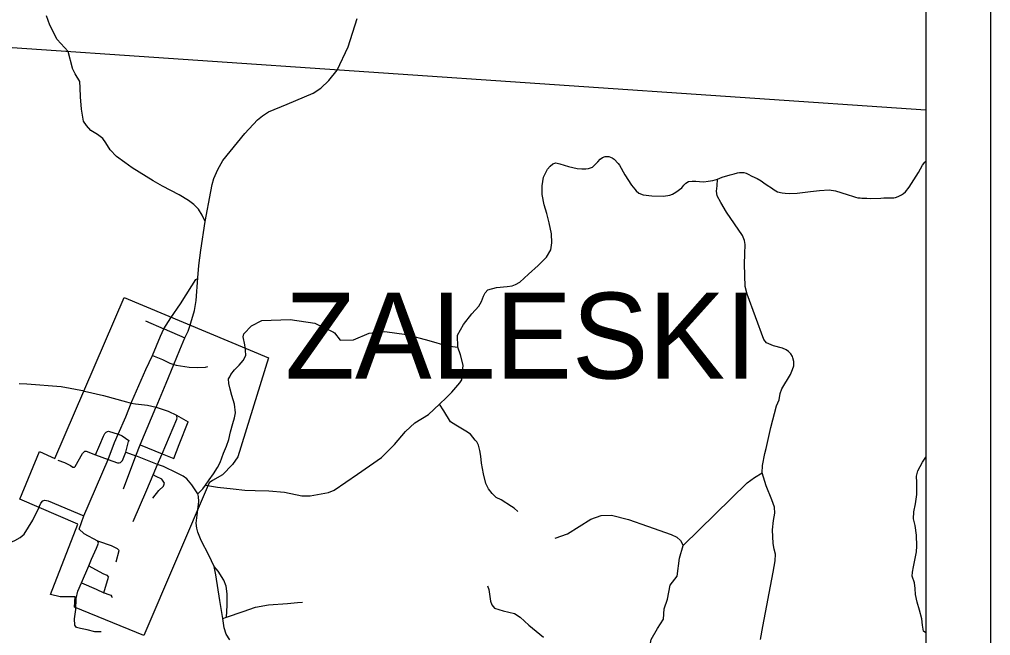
# Model space of a CAD drawing. Extents: x -22 to 431, y -18 to 160.
# Drawn here: x -16.478 to -14.978, y 26.647 to 27.599 of the extents above; entities that cross this region are included whole.
import ezdxf

# ---------------------------------------------------------------- set-up
doc = ezdxf.new("R2010")
doc.units = 0
for name, color, linetype in [('GM_X_Adjacent_County_Text', 7, 'Continuous'), ('GM_X_County_Road', 7, 'Continuous'), ('GM_X_County_ROW', 7, 'Continuous'), ('GM_X_County_Subdivision_Text', 7, 'Continuous'), ('GM_X_Interstate_Location', 7, 'Continuous'), ('GM_X_Major_River_Text', 7, 'Continuous'), ('GM_X_Minor_River_Text', 7, 'Continuous'), ('GM_X_Section', 7, 'Continuous'), ('GM_X_Section_Text', 7, 'Continuous'), ('GM_X_Township_ROW', 7, 'Continuous')]:
    doc.layers.add(name, color=color, linetype=linetype)

msp = doc.modelspace()

# ---------------------------------------------------------------- linework, layer by layer
at = {"layer": 'GM_X_Adjacent_County_Text'}
for points in [[(-16.3966, 27.5233), (-16.4032, 27.549), (-16.4203, 27.5675), (-16.4314, 27.5899), (-16.4368, 27.6045)], [(-16.1912, 27.2868), (-16.196, 27.2963), (-16.2017, 27.3056), (-16.2088, 27.3131), (-16.217, 27.3191), (-16.2316, 27.3279), (-16.2571, 27.3412), (-16.2716, 27.3495), (-16.3041, 27.3695), (-16.3153, 27.3776), (-16.3285, 27.387), (-16.3382, 27.3974), (-16.3449, 27.4079), (-16.3493, 27.4149), (-16.3575, 27.4211), (-16.368, 27.4271), (-16.3745, 27.4347), (-16.3793, 27.4417), (-16.3827, 27.4602), (-16.3841, 27.4793), (-16.3844, 27.493), (-16.3851, 27.5028), (-16.392, 27.5147), (-16.3965, 27.5229), (-16.3966, 27.5233)]]:
    msp.add_lwpolyline(points, dxfattribs=at)
at = {"layer": 'GM_X_County_Road'}
for points in [[(-16.1534, 27.0469), (-16.1517, 27.0502), (-16.1459, 27.0576), (-16.1386, 27.0645), (-16.1324, 27.0717), (-16.1287, 27.0795), (-16.1289, 27.0881), (-16.1303, 27.096), (-16.1325, 27.1085), (-16.1318, 27.1131), (-16.12, 27.1255), (-16.1036, 27.1336), (-16.06, 27.1352), (-16.0221, 27.1294), (-15.9929, 27.1158), (-15.9915, 27.1147), (-15.9826, 27.1032), (-15.9623, 27.1041), (-15.9378, 27.1143), (-15.9138, 27.1168), (-15.88, 27.1119), (-15.8457, 27.1027), (-15.8174, 27.0945), (-15.8009, 27.0927)], [(-15.5078, 26.8161), (-15.471, 26.8032), (-15.4627, 26.7993), (-15.4568, 26.7937), (-15.4526, 26.7863), (-15.3536, 26.8832), (-15.3424, 26.8915), (-15.3306, 26.8986)], [(-15.6505, 26.7975), (-15.6313, 26.8044), (-15.5953, 26.827), (-15.5796, 26.8325), (-15.5633, 26.8332), (-15.5372, 26.8265), (-15.5078, 26.8161)], [(-15.515, 26.5598), (-15.5145, 26.5612), (-15.5123, 26.5673), (-15.5034, 26.5778), (-15.5007, 26.5874), (-15.5053, 26.6078), (-15.5053, 26.623), (-15.502, 26.6409), (-15.4924, 26.6579), (-15.4831, 26.6724), (-15.4818, 26.6882), (-15.4771, 26.7031), (-15.4725, 26.7249), (-15.4621, 26.7389), (-15.4582, 26.7667), (-15.4526, 26.7863)], [(-15.7548, 26.7239), (-15.7528, 26.7185), (-15.7506, 26.7005), (-15.7482, 26.6944), (-15.7444, 26.6892), (-15.7309, 26.6853), (-15.7135, 26.6814), (-15.7046, 26.6758), (-15.691, 26.6634), (-15.6685, 26.6448)]]:
    msp.add_lwpolyline(points, dxfattribs=at)
at = {"layer": 'GM_X_County_ROW'}
for points in [[(-16.2151, 27.1252), (-16.2151, 27.1252), (-16.2079, 27.1494), (-16.2055, 27.1645), (-16.2026, 27.1998), (-16.2012, 27.2188), (-16.1981, 27.2426), (-16.1912, 27.2868), (-16.1827, 27.333), (-16.1807, 27.3438), (-16.178, 27.353), (-16.1718, 27.3669), (-16.1641, 27.3811), (-16.1298, 27.4227), (-16.1105, 27.4435), (-16.1027, 27.4499), (-16.0933, 27.456), (-16.0647, 27.4679), (-16.0246, 27.4847), (-16.0128, 27.4925), (-16, 27.5042), (-15.9876, 27.5206), (-15.9704, 27.5563), (-15.9565, 27.6004)], [(-16.2304, 27.0883), (-16.2228, 27.107), (-16.2175, 27.1172), (-16.2151, 27.1252)], [(-16.2674, 26.9995), (-16.2673, 26.9998), (-16.2514, 27.0367), (-16.2396, 27.0658), (-16.2304, 27.0883)], [(-16.2986, 26.9247), (-16.2916, 26.9415), (-16.2745, 26.9832), (-16.2675, 26.9995), (-16.2674, 26.9995)], [(-16.4481, 26.8452), (-16.4472, 26.8471), (-16.4451, 26.8514), (-16.4421, 26.8553), (-16.4391, 26.8565), (-16.434, 26.8554), (-16.3787, 26.832), (-16.341, 26.9192), (-16.327, 26.9141), (-16.3244, 26.9138), (-16.3221, 26.9146), (-16.3193, 26.9176), (-16.3137, 26.9305), (-16.2986, 26.9247)], [(-16.2537, 26.907), (-16.2537, 26.907), (-16.256, 26.908), (-16.2648, 26.9114), (-16.2986, 26.9247)], [(-16.2026, 26.8659), (-16.2056, 26.8706), (-16.2118, 26.8801), (-16.2196, 26.8893), (-16.2255, 26.8935), (-16.2365, 26.899), (-16.2537, 26.907)], [(-16.1532, 26.6406), (-16.1588, 26.6492), (-16.1619, 26.6589), (-16.1642, 26.6734), (-16.1689, 26.7012), (-16.175, 26.7408), (-16.1772, 26.754), (-16.1858, 26.7711), (-16.1975, 26.7937), (-16.2026, 26.8067), (-16.2043, 26.8131), (-16.2052, 26.8205), (-16.2025, 26.8414), (-16.2013, 26.8543), (-16.2014, 26.8617), (-16.2026, 26.8659)], [(-16.6958, 26.7206), (-16.6958, 26.7206), (-16.6767, 26.7252), (-16.6648, 26.7275), (-16.6534, 26.7331), (-16.6403, 26.742), (-16.6345, 26.7471), (-16.6308, 26.7505), (-16.6251, 26.7541), (-16.6051, 26.7605), (-16.5616, 26.7746), (-16.5542, 26.7758), (-16.5236, 26.7798), (-16.5155, 26.782), (-16.5012, 26.7874), (-16.4855, 26.7942), (-16.4773, 26.7985), (-16.4711, 26.8037), (-16.4575, 26.8254), (-16.4481, 26.8452)]]:
    msp.add_lwpolyline(points, dxfattribs=at)
at = {"layer": 'GM_X_County_Subdivision_Text'}
msp.add_lwpolyline([(-16.2862, 26.6473), (-16.3932, 26.6908), (-16.3924, 26.7069), (-16.4155, 26.7069), (-16.4304, 26.7105), (-16.388, 26.8194), (-16.4778, 26.8579), (-16.4475, 26.9314), (-16.4235, 26.9208), (-16.3164, 27.169), (-16.0936, 27.0762), (-16.1408, 26.9233), (-16.1492, 26.9112), (-16.1644, 26.8952), (-16.1799, 26.8865), (-16.1853, 26.8828)], close=True, dxfattribs=at)
at = {"layer": 'GM_X_Major_River_Text'}
msp.add_line((-15.0776, 27.4585), (-16.6991, 27.5692), dxfattribs=at)
at = {"layer": 'GM_X_Minor_River_Text'}
for points in [[(-15.8291, 27.0045), (-15.8186, 27.0148), (-15.81, 27.0233), (-15.7978, 27.0377), (-15.7949, 27.0419), (-15.7928, 27.065), (-15.7969, 27.0808), (-15.8009, 27.0927), (-15.8014, 27.1113), (-15.7922, 27.1273), (-15.779, 27.1438), (-15.7686, 27.1557), (-15.7641, 27.1633), (-15.761, 27.1713), (-15.7588, 27.1763), (-15.7543, 27.1809), (-15.7411, 27.1847), (-15.7247, 27.1864), (-15.7169, 27.1873), (-15.7118, 27.1892), (-15.7052, 27.1931), (-15.6918, 27.2053), (-15.6768, 27.2189), (-15.6641, 27.2314), (-15.6573, 27.2429), (-15.6555, 27.2536), (-15.6559, 27.2674), (-15.6596, 27.2844), (-15.6636, 27.299), (-15.6675, 27.3122), (-15.6708, 27.3283), (-15.6706, 27.3416), (-15.6684, 27.3549), (-15.6623, 27.3673), (-15.658, 27.3719), (-15.6539, 27.3756), (-15.6492, 27.3772), (-15.6434, 27.3755), (-15.6299, 27.3714), (-15.6166, 27.3683), (-15.609, 27.3678), (-15.603, 27.3681), (-15.5988, 27.3687), (-15.5928, 27.3705), (-15.589, 27.374), (-15.5845, 27.3788), (-15.5808, 27.3828), (-15.5771, 27.3855), (-15.5733, 27.3869), (-15.5676, 27.3872), (-15.5623, 27.3851), (-15.5592, 27.3829), (-15.5532, 27.3763), (-15.5513, 27.3737), (-15.5429, 27.3588), (-15.5325, 27.343), (-15.5276, 27.3365), (-15.5253, 27.334), (-15.5211, 27.3303), (-15.5144, 27.3279), (-15.5011, 27.3262), (-15.4831, 27.3258), (-15.4733, 27.3275), (-15.4692, 27.3291), (-15.4641, 27.3318), (-15.4549, 27.3384), (-15.4514, 27.343), (-15.4485, 27.3456), (-15.4446, 27.3482), (-15.4387, 27.349), (-15.4332, 27.3491), (-15.4272, 27.3484), (-15.4209, 27.3481), (-15.4139, 27.3488), (-15.4069, 27.3502), (-15.3995, 27.352), (-15.3922, 27.3549), (-15.3801, 27.3589), (-15.3739, 27.3603), (-15.3686, 27.3617), (-15.3656, 27.3621), (-15.3618, 27.3623), (-15.3589, 27.3622), (-15.3553, 27.3613), (-15.3523, 27.3598), (-15.3467, 27.3569), (-15.3383, 27.3528), (-15.3322, 27.3493), (-15.328, 27.3465), (-15.3227, 27.3429), (-15.3163, 27.3385), (-15.3119, 27.3353), (-15.3094, 27.3338), (-15.307, 27.3325), (-15.2995, 27.3307), (-15.2952, 27.3302), (-15.2891, 27.3299), (-15.2764, 27.3303), (-15.256, 27.3328), (-15.2422, 27.3347), (-15.227, 27.3353), (-15.217, 27.3339), (-15.1994, 27.3284), (-15.1893, 27.325), (-15.1861, 27.324), (-15.1829, 27.3233), (-15.1793, 27.323), (-15.1766, 27.3228), (-15.1732, 27.3227), (-15.169, 27.3227), (-15.1635, 27.3224), (-15.147, 27.3228), (-15.1425, 27.3231), (-15.1378, 27.3234), (-15.127, 27.3233), (-15.1243, 27.3237), (-15.1204, 27.3253), (-15.1151, 27.3278), (-15.1119, 27.33), (-15.1091, 27.3323), (-15.1033, 27.3396), (-15.0892, 27.3625), (-15.0828, 27.3738), (-15.0794, 27.3782), (-15.0776, 27.38)], [(-15.3245, 26.9362), (-15.3174, 26.9684), (-15.3086, 27.0019), (-15.3042, 27.0113), (-15.303, 27.021), (-15.3003, 27.028), (-15.2869, 27.0502), (-15.2835, 27.058), (-15.2818, 27.0637), (-15.2817, 27.0702), (-15.2832, 27.0761), (-15.2839, 27.0781), (-15.2863, 27.0823), (-15.2899, 27.086), (-15.2934, 27.0883), (-15.2991, 27.091), (-15.3128, 27.0948), (-15.324, 27.0991), (-15.3281, 27.1045), (-15.3538, 27.1746), (-15.3566, 27.1863), (-15.3577, 27.2208), (-15.3575, 27.2368), (-15.3568, 27.251), (-15.358, 27.2573), (-15.3611, 27.265), (-15.3857, 27.3011), (-15.3945, 27.3162), (-15.3999, 27.3264), (-15.401, 27.3336), (-15.4002, 27.3419), (-15.3995, 27.352)], [(-16.2442, 27.1378), (-16.2297, 27.1596), (-16.2119, 27.1874), (-16.2056, 27.1969), (-16.2027, 27.1987)], [(-16.1909, 26.8794), (-16.1851, 26.8878), (-16.1786, 26.8969), (-16.1724, 26.9065), (-16.1681, 26.9143), (-16.1631, 26.9287), (-16.1585, 26.9397), (-16.155, 26.95), (-16.1521, 26.962), (-16.1488, 26.9745), (-16.146, 26.9836), (-16.1447, 26.991), (-16.1462, 27.0043), (-16.1501, 27.0177), (-16.1526, 27.0276), (-16.155, 27.0365), (-16.1552, 27.0435), (-16.1534, 27.0468), (-16.1534, 27.0469)], [(-16.378, 27.0248), (-16.4138, 27.0313), (-16.4672, 27.0352), (-16.479, 27.0361)], [(-16.2026, 26.8659), (-16.1952, 26.8735), (-16.1909, 26.8794), (-16.1721, 26.8761), (-16.1483, 26.8735), (-16.1303, 26.8717), (-16.1142, 26.8711), (-16.0932, 26.8705), (-16.0687, 26.8687), (-16.0422, 26.8627), (-16.0289, 26.8628), (-16.0008, 26.8679), (-15.9919, 26.8716), (-15.956, 26.8965), (-15.9189, 26.9224), (-15.8988, 26.942), (-15.8818, 26.9625), (-15.8675, 26.9755), (-15.8464, 26.9887), (-15.8291, 27.0045)], [(-15.7081, 26.8388), (-15.714, 26.8438), (-15.7178, 26.8464), (-15.7337, 26.8568), (-15.7414, 26.8605), (-15.7477, 26.8667), (-15.7537, 26.8735), (-15.7578, 26.8821), (-15.7612, 26.8967), (-15.7641, 26.9134), (-15.7652, 26.9242), (-15.7671, 26.9331), (-15.7691, 26.9414), (-15.7716, 26.9461), (-15.774, 26.9487), (-15.7811, 26.9581), (-15.7883, 26.9627), (-15.8041, 26.9723), (-15.812, 26.9773), (-15.8226, 26.9943), (-15.8291, 27.0045)], [(-15.3333, 26.6412), (-15.3293, 26.6613), (-15.3134, 26.7453), (-15.3103, 26.7626), (-15.3102, 26.7726), (-15.3122, 26.7806), (-15.3137, 26.7891), (-15.3144, 26.8103), (-15.3131, 26.825), (-15.3111, 26.836), (-15.3116, 26.8455), (-15.3154, 26.8568), (-15.3243, 26.8783), (-15.3286, 26.8918), (-15.3306, 26.8986), (-15.3302, 26.91), (-15.3262, 26.9285), (-15.3245, 26.9362)], [(-15.0776, 26.6511), (-15.081, 26.654), (-15.0827, 26.6631), (-15.0836, 26.6729), (-15.0874, 26.6865), (-15.091, 26.6986), (-15.0934, 26.7104), (-15.0941, 26.7197), (-15.095, 26.7288), (-15.0988, 26.7388), (-15.0981, 26.7452), (-15.0967, 26.7532), (-15.0923, 26.7762), (-15.0917, 26.7854), (-15.0919, 26.8024), (-15.0942, 26.817), (-15.0965, 26.8276), (-15.096, 26.8383), (-15.0938, 26.8506), (-15.0917, 26.8651), (-15.0914, 26.8738), (-15.0916, 26.8837), (-15.0921, 26.8932), (-15.0901, 26.9015), (-15.0826, 26.9149), (-15.0776, 26.9226)], [(-16.3521, 26.6529), (-16.3621, 26.6527), (-16.3739, 26.6562), (-16.3839, 26.6582), (-16.39, 26.6597), (-16.3927, 26.6631), (-16.3933, 26.6729), (-16.3914, 26.6875)], [(-16.1642, 26.6734), (-16.1582, 26.6757), (-16.1328, 26.6842), (-16.1137, 26.6911), (-16.0934, 26.6947), (-16.0641, 26.6969), (-16.0488, 26.6982), (-16.0407, 26.6986)]]:
    msp.add_lwpolyline(points, dxfattribs=at)
at = {"layer": 'GM_X_Section'}
for p, q in [((-14.9776, 29.1642), (-14.9776, 22.1642)), ((-15.0776, 29.0642), (-15.0776, 22.2642)), ((-15.0776, 29.0642), (-15.0776, 22.2642))]:
    msp.add_line(p, q, dxfattribs=at)
at = {"layer": 'GM_X_Section_Text'}
for points in [[(-16.3046, 27.0088), (-16.283, 27.0582), (-16.273, 27.0799), (-16.2604, 27.1093), (-16.2552, 27.1209), (-16.2442, 27.1378)], [(-16.2837, 27.1331), (-16.2552, 27.1209), (-16.2546, 27.1207), (-16.2228, 27.107)], [(-16.273, 27.0799), (-16.2575, 27.0735), (-16.2468, 27.0683), (-16.2458, 27.068), (-16.2457, 27.0679)], [(-16.2457, 27.0679), (-16.2396, 27.0658), (-16.2364, 27.0648), (-16.216, 27.0617), (-16.2029, 27.0612), (-16.191, 27.0617), (-16.187, 27.0628)], [(-16.378, 27.0248), (-16.3485, 27.0181), (-16.3128, 27.0079), (-16.3057, 27.0063), (-16.2988, 27.0051), (-16.2807, 27.0032), (-16.2673, 26.9998), (-16.2669, 26.9997), (-16.2487, 26.9935), (-16.2357, 26.9875), (-16.2321, 26.9857), (-16.2176, 26.9774)], [(-16.341, 26.9192), (-16.3313, 26.9452), (-16.3257, 26.9582), (-16.3141, 26.9852), (-16.3057, 27.0063), (-16.3046, 27.0088), (-16.3046, 27.0088)], [(-16.3027, 26.8234), (-16.2816, 26.8723), (-16.2718, 26.8952), (-16.2648, 26.9114), (-16.2582, 26.9268), (-16.2579, 26.9277), (-16.235, 26.9814), (-16.2348, 26.9835), (-16.2357, 26.9875)], [(-16.2313, 26.9423), (-16.2176, 26.9774)], [(-16.3607, 26.9261), (-16.3539, 26.9416), (-16.3483, 26.9552), (-16.3462, 26.9591), (-16.3444, 26.9614), (-16.3425, 26.9621)], [(-16.3425, 26.9621), (-16.3405, 26.9629), (-16.3257, 26.9582), (-16.3255, 26.9582), (-16.3197, 26.9558), (-16.3095, 26.9484), (-16.3097, 26.9467)], [(-16.3137, 26.9305), (-16.3097, 26.9467)], [(-16.2916, 26.9415), (-16.2579, 26.9277), (-16.2399, 26.9204)], [(-16.2399, 26.9204), (-16.2313, 26.9423), (-16.2313, 26.9423)], [(-16.4192, 26.9179), (-16.4088, 26.9142), (-16.3996, 26.9096), (-16.396, 26.9073), (-16.3947, 26.9073), (-16.3933, 26.9074), (-16.3921, 26.9082), (-16.3807, 26.9282), (-16.3784, 26.931), (-16.3772, 26.9318), (-16.3754, 26.9319), (-16.3607, 26.9261), (-16.341, 26.9192)], [(-16.3178, 26.8738), (-16.2986, 26.9247)], [(-16.2721, 26.8595), (-16.2629, 26.8712), (-16.2558, 26.8781), (-16.2543, 26.8825), (-16.2582, 26.8888), (-16.2672, 26.893), (-16.2718, 26.8952)], [(-16.3861, 26.8113), (-16.3787, 26.832)], [(-16.3861, 26.8113), (-16.3787, 26.8048), (-16.3575, 26.7936)], [(-16.3914, 26.6875), (-16.3906, 26.7043), (-16.388, 26.7155), (-16.3825, 26.7284), (-16.3712, 26.7549), (-16.3668, 26.7653), (-16.3593, 26.7819), (-16.3562, 26.79), (-16.3575, 26.7936)], [(-16.3575, 26.7936), (-16.356, 26.7931), (-16.3365, 26.786), (-16.3276, 26.7814), (-16.3243, 26.7783)], [(-16.3288, 26.7611), (-16.3243, 26.7783)], [(-16.3712, 26.7549), (-16.3494, 26.7431), (-16.3431, 26.7402), (-16.3407, 26.7374)], [(-16.3481, 26.7132), (-16.3407, 26.7374)], [(-16.3825, 26.7284), (-16.3596, 26.7186), (-16.3481, 26.7132), (-16.3476, 26.713), (-16.34, 26.7107), (-16.3372, 26.7095), (-16.3355, 26.7068), (-16.3351, 26.7061)]]:
    msp.add_lwpolyline(points, dxfattribs=at)
at = {"layer": 'GM_X_Township_ROW'}
msp.add_lwpolyline([(-16.1582, 26.6757), (-16.1573, 26.6934), (-16.1575, 26.7115), (-16.1589, 26.7234), (-16.1626, 26.7328), (-16.1712, 26.7466), (-16.1772, 26.754)], dxfattribs=at)

# ---------------------------------------------------------------- texts
at = {"layer": 'GM_X_Interstate_Location'}
msp.add_text('ZALESKI', height=0.13258, rotation=0, dxfattribs=at).set_placement((-16.068, 27.0441))

doc.saveas('drawing.dxf')
